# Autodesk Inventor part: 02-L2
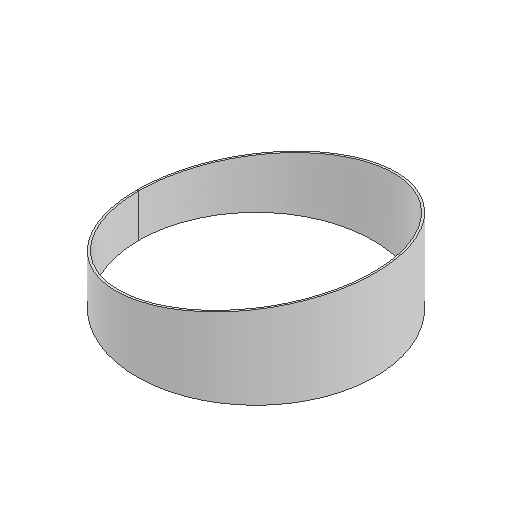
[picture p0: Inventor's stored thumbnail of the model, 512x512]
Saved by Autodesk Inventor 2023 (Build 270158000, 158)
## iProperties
Created: 2023-01
Part Number: 02-L2
Material: Generic
Document SubType Name: Sheet Metal
Designer: Nelson C Agudelo A
Density: 1 g/cm^3
Flat Pattern Width: 10.2937 cm
Flat Pattern Length: 84.8759 cm
Flat Pattern Area: 873.689 cm^2
Sheet Metal Rule: Default_mm
Sheet Metal Width: 102,937 mm
Sheet Metal Length: 848,759 mm
Sheet Metal Area: 87368,870 mm^2
Appearance: Default
Author: Nelson C Agudelo A
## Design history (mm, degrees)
derived "01-Esquema Codo Mitrado.ipt"
  sketch "Sketch1"
    geometry: L1 (0, 0)-(381, 0) reference; L2 (381, 0)-(381, 75.786) reference; L3 (244.5, 0)-(244.5, 48.634) reference; L4 (517.5, 0)-(517.5, 102.937) reference; L5 (0, 0)-(517.5, 102.937) reference; L6 (0, 0)-(0, 381) reference; L7 (0, 244.5)-(48.634, 244.5) reference; L8 (0, 517.5)-(102.937, 517.5) reference; L9 (0, 381)-(0, 517.5) reference; L10 (0, 0)-(102.937, 517.5) reference; L11 (0, 381)-(75.786, 381) reference; L12 (0, 0)-(322.996, 215.819) reference; L13 (381, 75.786)-(322.996, 215.819) reference; L14 (0, 0)-(351.998, 145.802) reference; L15 (517.5, 0)-(898.5, 0) reference; L16 (381, 0)-(762, 0) reference; L17 (762, 0)-(1143, 0) reference; 1 further point
node "Contour Flange1"
  sketch "Sketch2"
    geometry: L1 (-381, 0)-(-244.5, -0.05); L2 (-381, 0)-(-244.5, 0.05); L3 (-244.5, -0.05)-(-244.5, 0.05); A1 r 136.5 centre (-381, 0) between (-244.5, 0) and (-244.5, 0.05); A2 r 136.5 centre (-381, 0) between (-244.5, 0.05) and (-244.5, -0.05); 2 further points
    constraints: 6 end point, 4 point on circle, 2 centre point, 1 coincident, 1 midpoint, 1 vertical
    dimensions: "d7" = 273 diameter of A1 (= ODtuberia); "d10" = 0.1 distance of L1.end L2.end
sketch "Sketch3"
  geometry: L1 (0, 0)-(517.5, 102.937); L2 (517.5, 102.937)-(517.5, 0) reference; L3 (0, 0)-(517.5, 217.873); L4 (517.5, 102.937)-(244.5, 102.937) reference; L5 (517.5, 217.873)-(517.5, 102.937)
  constraints: 6 end point, 2 point on line, 1 collinear
cut "Cut1" sketch "Sketch3" dims "d24" = 2.5 (= Thickness), "d25" = 0
body "Solid1"
face "Plate1" dims "d11" = 2.5 (= Thickness), "d12" = 2.5 (= BendReliefWidth), "d15" = 1.25 (= BendReliefDepth), "d16" = 5 (= MinimumRemnant), "d17" = 2.5 (= TransitionRadius), "d18" = 102.93715 (= L2 + Recorte), "d19" = 2.5 (= BendRadius), "d20" = 2.5, "d21" = 10 (= CornerReliefSize), "d22" = 2.5 (= GapSize), "d23" = 2.5 (= JacobiRadiusSize), "SeamGap" = 0.01
bend "Bend1" dims "d11" = 2.5 (= Thickness), "d12" = 2.5 (= BendReliefWidth), "d15" = 1.25 (= BendReliefDepth), "d16" = 5 (= MinimumRemnant), "d17" = 2.5 (= TransitionRadius), "d19" = 2.5 (= BendRadius), "d20" = 2.5, "SeamGap" = 0.01
feature "Corner1" dims "d20" = 2.5, "d21" = 10 (= CornerReliefSize), "d22" = 2.5 (= GapSize), "d23" = 2.5 (= JacobiRadiusSize)
feature "Definition1"
other parameters: "Thickness" = 2.5 (derived), "BendRadius" = 2.5 (= Thickness), "BendReliefWidth" = 2.5 (= Thickness), "BendReliefDepth" = 1.25 (= 0.5 x Thickness), "MinimumRemnant" = 5 (= 2 x Thickness), "TransitionRadius" = 2.5 (= BendRadius), "JacobiRadiusSize" = 2.5 (= BendRadius), "GapSize" = 2.5 (= Thickness), "d1" = 381, "d2" = 75.78561, "d3" = 90 deg, "d4" = 273, "d5" = 136.5, "d6" = 273, "d8" = 273, "d9" = 136.5, "DL1" = 22.5 deg, "d13" = 151.57122, "L2" = 75.78561, "L1" = 151.57122, "Recorte" = 27.15154, "D" = 90 deg, "E1" = 381, "ODtuberia" = 273, "DL2" = 1.9635, "d14" = 27.15154, "BendRadius" = 2.5, "BendReliefDepth" = 1.25, "BendReliefWidth" = 2.5, "D" = 90 deg, "DL1" = 22.5 deg, "DL2" = 1.9635, "E1" = 381, "GapSize" = 2.5, "JacobiRadiusSize" = 2.5, "L1" = 151.57122, "L2" = 75.78561, "MinimumRemnant" = 5, "ODtuberia" = 273, "Recorte" = 27.15154, "Thickness" = 2.5, "TransitionRadius" = 2.5
